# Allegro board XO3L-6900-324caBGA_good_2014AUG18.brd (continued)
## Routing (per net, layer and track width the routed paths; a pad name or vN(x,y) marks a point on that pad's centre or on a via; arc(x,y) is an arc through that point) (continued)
PT32B: length 11.2
  TOP w0.102: BGA.C13 v1(22.72,25.12)
  BOTTOM w0.152: v1(22.72,25.12) 22.72,25.24 23.12,25.64 23.12,26.22 23.41,26.52 23.41,35.45
PT33A: length 10.2
  TOP w0.102: BGA.B14 v1(23.52,25.92)
  L3_SIGNAL w0.152: v1(23.52,25.92) 23.81,26.21 23.81,35.47
PT33B: length 10.2
  TOP w0.102: BGA.B15 v1(24.32,25.92)
  L3_SIGNAL w0.152: v1(24.32,25.92) 24.06,26.18 24.06,35.47
PT33C: length 12
  TOP w0.102: BGA.E12 v1(21.92,24.32)
  L4_SIGNAL w0.152: v1(21.92,24.32) 22.32,24.72 22.32,27.07 22.02,27.37 22.02,35.46
PT33D: length 12.8
  TOP w0.102: BGA.F12 v1(21.92,23.52)
  L4_SIGNAL w0.152: v1(21.92,23.52) 21.52,23.92 21.52,27.08 21.77,27.33 21.77,35.46
PT34A: length 12
  TOP w0.102: BGA.C14 v1(23.52,25.12)
  L3_SIGNAL w0.152: v1(23.52,25.12) BGA.C14 24.54,25.52 25.17,26.16 25.17,35.47
PT34B: length 11.5
  TOP w0.102: BGA.C15 v1(24.32,25.12)
  L3_SIGNAL w0.152: 25.43,35.47 25.43,26.05 24.64,25.27 24.47,25.27 v1(24.32,25.12)
PT34C: length 12
  TOP w0.102: BGA.D13 v1(22.72,24.32)
  L4_SIGNAL w0.152: v1(22.72,24.32) BGA.D13 23.12,26.4 23.37,26.65 23.37,35.45
PT34D: length 13.5
  TOP w0.102: BGA.E13 v1(22.72,23.52)
  L4_SIGNAL w0.152: 23.62,35.45 23.62,26.72 23.92,26.42 23.92,24.12 23.72,23.92 23.43,23.92 BGA.E13 v1(22.72,23.52)
PT35A: length 8.4
  TOP w0.152: BGA.A15 24.97,27.37 24.97,35.46
PT35B: length 8.5
  TOP w0.152: 25.23,35.46 25.23,27.41 BGA.A16
PT35C: length 12.5
  TOP w0.102: BGA.D14 v1(23.52,24.32)
  BOTTOM w0.152: 24.93,35.45 24.93,25.92 24.52,25.52 24.15,25.52 23.92,25.29 23.92,25.28 BGA.D14 v1(23.52,24.32)
PT35D: length 12.1
  TOP w0.102: BGA.D15 v1(24.32,24.32)
  BOTTOM w0.152: 25.18,35.45 25.18,25.82 24.72,25.36 24.72,24.92 24.32,24.52 v1(24.32,24.32)
PT36A: length 9.3
  TOP w0.152: 25.92,35.46 25.92,26.72 BGA.B16
PT36B: length 8.4
  TOP w0.152: BGA.A17 26.17,27.27 26.17,35.46
PT36C: length 11.8
  TOP w0.102: BGA.C16 v1(25.12,25.12)
  L3_SIGNAL w0.152: 35.97,26.07 26.72,26.07 26.02,25.37 25.37,25.37 v1(25.12,25.12)
PT36D: length 14.2
  TOP w0.102: BGA.E14 v1(23.52,23.52)
  L3_SIGNAL w0.152: v1(23.52,23.52) BGA.E14 24.15,23.92 24.52,23.92 24.72,24.12 24.72,24.15 24.72,24.15 24.72,24.57 24.87,24.72 24.95,24.72 25.4,24.72 25.79,25.12 26.15,25.12 26.86,25.82 35.97,25.82

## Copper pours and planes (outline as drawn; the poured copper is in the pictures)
GND on L2_GND: 1.92,2.52 1.92,38.77 39.64,38.77 39.64,2.52
VCC on L5_PWR: 21.59,5.41 21.59,18.02 21.25,18.35 18.35,18.35 18.35,19.05 19.18,19.05 19.18,20.38 18.41,21.15 18.41,21.53 21.29,21.53 21.59,21.83 21.59,35.21 34.51,35.21 34.51,21.59 22.67,21.59 20.76,19.68 20.76,19.37 20.94,19.19 22.64,19.19 25.57,16.26 34.5,16.26 34.5,5.41
VCCIO0 on L5_PWR: 18.41,21.65 18.41,22.29 19.11,22.29 19.11,24.89 5.66,24.89 5.66,35.21 21.46,35.21 21.46,21.91 21.21,21.65
VCCIO1 on L5_PWR: 20.89,19.41 20.89,19.62 22.73,21.46 34.51,21.46 34.51,16.38 25.65,16.38 22.73,19.3 21,19.3
VCCIO2 on L5_PWR: 18.35,18.22 21.21,18.22 21.46,17.97 21.46,5.41 5.63,5.41 5.63,16.26 16.38,16.26
VCCIO3 on L5_PWR: 5.64,16.39 5.64,19.81 17.97,19.81 18.22,19.56 18.22,18.29 16.32,16.39
VCCIO4 on L5_PWR: 5.64,19.94 5.64,21.46 18.29,21.46 18.29,21.08 19.05,20.32 19.05,19.18 18.35,19.18 18.35,19.62 18.03,19.94
VCCIO5 on L5_PWR: 5.66,21.59 5.66,24.76 18.99,24.76 18.99,22.42 18.29,22.42 18.29,21.59

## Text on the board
User.Comments: RP | RCI | 08/18/14 | DWG NO: | XO3L-69E-400caBGA | REVISION | 1.0 | SHEET | 1 | OF | XO3L-69E-400CABGA PCB BREAKOUT | LATTICE SEMICONDUCTOR CORPORATION
Ref Des/Silkscreen Top: PCB BREAKOUT | XO3L-69E-324CABGA | SEMICONDUCTOR | LATTICE | A | B | C | D | E | F | G | H | J | K | L | M | N | P | R | T | U | V | 1 | 2 | 3 | 4 | 5 | 6 | 7 | 8 | 9 | 10 | 11 | 12 | 13 | 14 | 15 | 16 | 17 | 18
PAGE_OUTLINE: 1 | INITIAL RELEASE | MM/DD/YYYY | XXXX XXXXX | SPECIAL INSTRUCTIONS: | 1/2 CU OZ FOR INTERNAL AND EXTERNAL LAYERS | MIN BOARD THICKNESS IS 62MILS. | DESIGNED BY: | APPROVED BY: | SIGNATURES         DATE | REV | DESCRIPTION | ESCAPE VIA DRILL | TRACE WIDTH/SPACE | ESCAPE VIA PAD | ARRAY SIZE | BGA LAND OPENING | BGA LAND PAD | PACKAGE SIZE | PITCH | SIGNAL         (L4) | SIGNAL         (L3) | GND     PLANE  (L2) | POWER   PLANE  (L5) | PRIMARY SIDE   (L1) | SECONDARY SIDE (L6) | SECONDARY SILKSCREEN | SECONDARY SOLDERMASK | PRIMARY SOLDERMASK | PRIMARY SILKSCREEN | 0.8 | 18 X 18 | 15 X 15 | 0.4064 | 0.4572 | 0.254 | 0.15/0.10 | 0.5334 | MM | DATE | 708.66 X 708.66 | 590.55 X 590.55 | 31.5 | 6/4 | 21 | 16 | 10 | 18 | MILS | APPROVED | PCB BREAKOUT DETAILS | 6 LAYER STACKUP | REVISION
BODY_CENTER: FIGURE | SIZE | 10.0 | ALL UNITS ARE IN MILS | SIZE MM | 0.254 | PLATED | QTY | 83 | DRILL CHART: TOP to L4_SIGNAL
PLACE_BOUND_TOP: FIGURE | SIZE | 10.0 | ALL UNITS ARE IN MILS | SIZE MM | 0.254 | PLATED | QTY | 116 | DRILL CHART: TOP to L3_SIGNAL
DISPLAY_TOP: FIGURE | SIZE | 10.0 | ALL UNITS ARE IN MILS | SIZE MM | 0.254 | PLATED | QTY | 50 | DRILL CHART: TOP to BOTTOM
